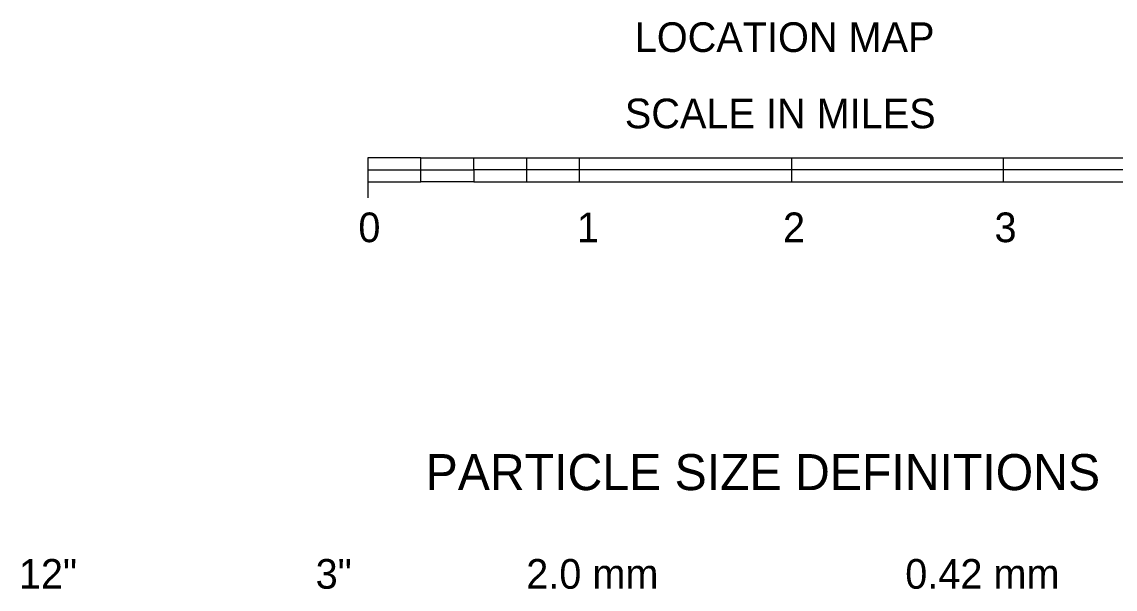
# Model space of a CAD drawing. Extents: x 0 to 34, y 0 to 22.
# Drawn here: x 23.78 to 28.94, y 11.19 to 13.86 of the extents above; entities that cross this region are included whole.
import ezdxf

# ---------------------------------------------------------------- set-up
doc = ezdxf.new("R2010")
doc.units = 0
doc.layers.add('SH_Data', color=7, linetype='Continuous')
doc.layers.add('SH_Text', color=7, linetype='Continuous')

msp = doc.modelspace()

# ---------------------------------------------------------------- linework, layer by layer
at = {"layer": 'SH_Data'}
for p, q in [((25.6667, 13.22), (25.4167, 13.22)), ((25.4167, 13.22), (25.4167, 13.1638)), ((25.6667, 13.22), (25.9167, 13.22)), ((25.6667, 13.1638), (25.6667, 13.22)), ((25.9167, 13.1638), (25.9167, 13.22)), ((25.9167, 13.22), (26.1667, 13.22)), ((26.1667, 13.22), (26.4167, 13.22)), ((26.1667, 13.22), (26.1667, 13.1638)), ((26.4167, 13.1638), (26.4167, 13.22)), ((26.4167, 13.22), (27.4167, 13.22)), ((27.4167, 13.22), (28.4167, 13.22)), ((27.4167, 13.22), (27.4167, 13.1638)), ((28.4167, 13.1638), (28.4167, 13.22)), ((28.4167, 13.22), (29.4167, 13.22)), ((25.4167, 13.1638), (25.4167, 13.0325)), ((25.4167, 13.1638), (25.6667, 13.1638)), ((25.6667, 13.1638), (25.9167, 13.1638)), ((25.6667, 13.1075), (25.6667, 13.1638)), ((25.9167, 13.1638), (25.9167, 13.1075)), ((26.1667, 13.1638), (25.9167, 13.1638)), ((26.4167, 13.1638), (26.1667, 13.1638)), ((26.1667, 13.1638), (26.1667, 13.1075)), ((26.4167, 13.1075), (26.4167, 13.1638)), ((27.4167, 13.1638), (26.4167, 13.1638)), ((28.4167, 13.1638), (27.4167, 13.1638)), ((27.4167, 13.1638), (27.4167, 13.1075)), ((28.4167, 13.1075), (28.4167, 13.1638)), ((29.4167, 13.1638), (28.4167, 13.1638)), ((25.4167, 13.1075), (25.6667, 13.1075)), ((25.9167, 13.1075), (25.6667, 13.1075)), ((25.9167, 13.1075), (26.1667, 13.1075)), ((26.1667, 13.1075), (26.4167, 13.1075)), ((26.4167, 13.1075), (27.4167, 13.1075)), ((27.4167, 13.1075), (28.4167, 13.1075)), ((28.4167, 13.1075), (29.4167, 13.1075))]:
    msp.add_line(p, q, dxfattribs=at)

# ---------------------------------------------------------------- texts
at = {"layer": 'SH_Text'}
for s, height, p in [('LOCATION MAP', 0.14, (26.677, 13.72)), ('SCALE IN MILES', 0.14, (26.6302, 13.36)), ('0', 0.14, (25.3726, 12.8225)), ('1', 0.14, (26.4037, 12.8225)), ('2', 0.14, (27.3766, 12.8225)), ('3', 0.14, (28.3748, 12.8225)), ('PARTICLE SIZE DEFINITIONS', 0.17, (25.6902, 11.6525)), ('12"', 0.14, (23.7701, 11.1873)), ('3"', 0.14, (25.1709, 11.1873)), ('2.0 mm', 0.14, (26.1647, 11.1873)), ('0.42 mm', 0.14, (27.9535, 11.1873))]:
    msp.add_text(s, height=height, dxfattribs=at).set_placement(p)

doc.saveas('drawing.dxf')
